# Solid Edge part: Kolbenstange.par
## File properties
Username: ahadarics
Dokumentum tartalom típus: 0
Author: ahadarics
Last saved by: ahadarics
Revision: 84
Sűrűség: 0,000 kg/m^3
Pontosság: 0,990
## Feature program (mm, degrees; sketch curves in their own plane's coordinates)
base feature "unnamed BaseFeature 1"
thread "unnamed Thread 1"
chamfer "Letörés_1" setback 0.5
sketch for "Kihúzás_1" plane through (48, 0, 0) normal (1, 0, 0) x-axis (0, -1, 0)
  circle centre (0, 0) radius 8
extrude "Kihúzás_1" add finite 26.5 along -normal
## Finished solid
Body 1: solid body, 13 faces, 23 edges, 12 vertices.
  Faces by surface: plane 9, cylinder 3, cone 1
  Edges by curve: line 12, circle 11
Bounding box of the edges (mm): 325.000 x 16.000 x 16.000, from (-277, -8, -8) to (48, 8, 8).
Cylindrical faces by radius (mm): R3 x2, R8 x1
Conical faces (half-angle, radius in mm at the cone's reference point): 45 deg R2.5 x1
Planar faces by outward normal: +x 3, +z 1, -x 4, -z 1
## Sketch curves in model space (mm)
circle centre (48, 0, 0) radius 8
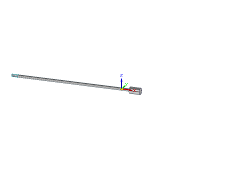
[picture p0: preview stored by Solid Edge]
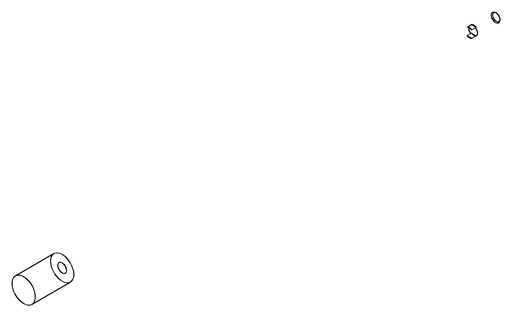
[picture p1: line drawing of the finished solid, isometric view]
